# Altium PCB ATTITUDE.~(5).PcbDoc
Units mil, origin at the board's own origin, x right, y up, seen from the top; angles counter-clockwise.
Board outline 6000 x 4000 mil, 2 copper layers (Top Layer, Bottom Layer); 6 components, 40 nets, 83 pads, 0 vias.
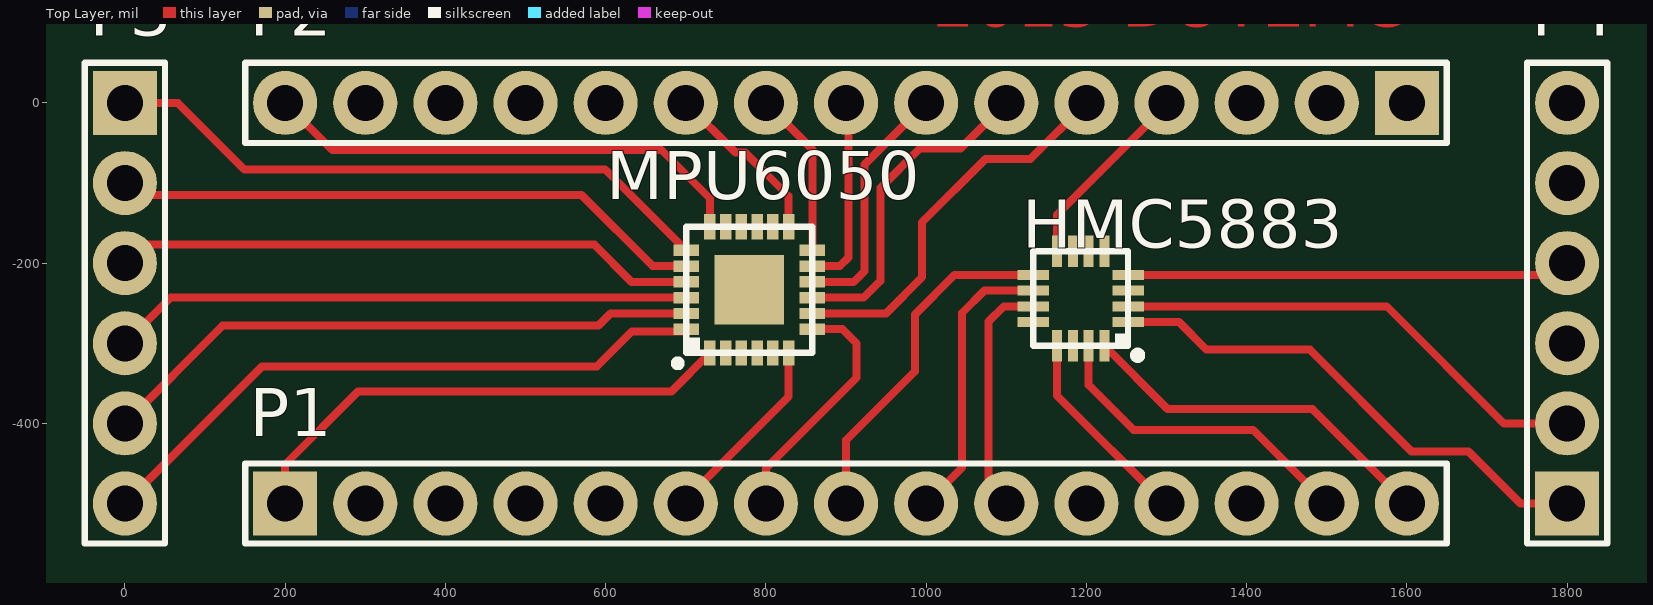
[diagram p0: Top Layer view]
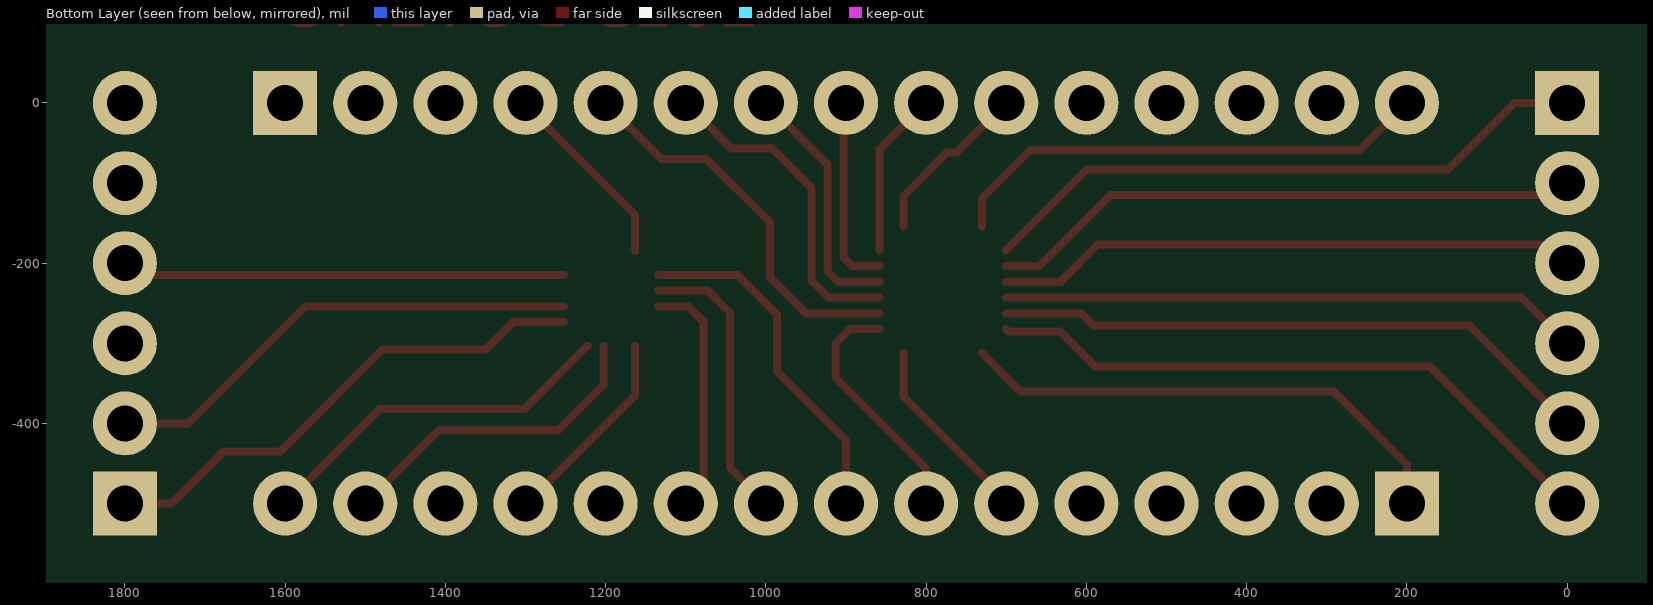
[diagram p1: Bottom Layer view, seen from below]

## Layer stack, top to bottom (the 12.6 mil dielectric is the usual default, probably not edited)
Top Solder: solder mask 0.4, Solder Resist, Dk 3.5
Top Layer: signal copper 1.4
Dielectric 1: dielectric 12.6, FR-4, Dk 4.8
Bottom Layer: signal copper 1.4
Bottom Solder: solder mask 0.4, Solder Resist, Dk 3.5

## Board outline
-436,-2862 5564,-2862 5564,1138 -436,1138

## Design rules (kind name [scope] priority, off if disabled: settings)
Clearance [All] p1: gap=10
PolygonConnect [All] p1: connectstyle=Relief reliefconductorwidth=10 reliefentries=4 polygonreliefangle="90 Angle" airgapwidth=10
RoutingVias [All] p1: holewidth=28 width=50 viastyle="Through Hole" minholewidth=28 minwidth=50 maxholewidth=28 maxwidth=50
SolderMaskExpansion [All] p1: expansion=4
Width [All] p1: maxlimit=10 minlimit=10 preferedwidth=10
29 further rules are at their usual default settings.

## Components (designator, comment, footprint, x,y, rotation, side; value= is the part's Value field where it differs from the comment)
HMC5883 "HMC5883" HMC5883 1252,-185 r180 top
MPU6050 "MPU6050" MPU6050 858,-312 r90 top
P1 "Header 15" HDR1X15 200,-500 r0 top
P2 "Header 15" HDR1X15 1600,0 r180 top
P3 "Header 6" HDR1X6 0,0 r270 top
P4 "Header 6" HDR1X6 1800,-500 r90 top

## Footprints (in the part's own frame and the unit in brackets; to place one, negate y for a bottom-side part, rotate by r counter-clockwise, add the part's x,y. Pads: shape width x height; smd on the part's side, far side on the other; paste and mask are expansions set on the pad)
HDR1X6 [mil] "Connector; Header; 6 Position"
  rect 80x80 hole 45: 1(0,0)
  round 80 hole 45: 2(100,0) 3(200,0) 4(300,0) 5(400,0) 6(500,0)
  silkscreen extent -50,-50 550,50
HDR1X15 [mil] "Connector; Header; 15 Position"
  rect 80x80 hole 45: 1(0,0)
  round 80 hole 45: 2(100,0) 3(200,0) 4(300,0) 5(400,0) 6(500,0) 7(600,0) 8(700,0) 9(800,0) 10(900,0) 11(1000,0) 12(1100,0) 13(1200,0) 14(1300,0) 15(1400,0)
  silkscreen extent -50,-50 1450,50
HMC5883 [mm]
  rect 1x0.32 smd: 1(0,2.25) 2(0,1.75) 3(0,1.25) 4(0,0.75) 9(3,0.75) 10(3,1.25) 11(3,1.75) 12(3,2.25)
  rect 0.32x1 smd: 5(0.75,0) 6(1.25,0) 7(1.75,0) 8(2.25,0) 13(2.25,3) 14(1.75,3) 15(1.25,3) 16(0.75,3)
  silkscreen extent -0.42,0 3,3.42
MPU6050 [mm]
  rect 0.8x0.36 smd: 1(0,3.25) 2(0,2.75) 3(0,2.25) 4(0,1.75) 5(0,1.25) 6(0,0.75) 13(4,0.75) 14(4,1.25) 15(4,1.75) 16(4,2.25) 17(4,2.75) 18(4,3.25)
  rect 0.36x0.8 smd: 7(0.75,0) 8(1.25,0) 9(1.75,0) 10(2.25,0) 11(2.75,0) 12(3.25,0) 19(3.25,4) 20(2.75,4) 21(2.25,4) 22(1.75,4) 23(1.25,4) 24(0.75,4)
  rect 2.2x2.2 smd: 25(2,2)
  silkscreen extent -0.42,0 4,4.36

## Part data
HMC5883 MPU6050: library part Component_1
P1 P2: "Header, 15-Pin"
P3 P4: "Header, 6-Pin"

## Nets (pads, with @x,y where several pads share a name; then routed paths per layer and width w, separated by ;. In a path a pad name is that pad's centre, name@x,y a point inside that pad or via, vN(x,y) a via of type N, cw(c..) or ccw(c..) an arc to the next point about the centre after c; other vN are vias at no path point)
HMC_1: HMC5883.1 P4.1 | length 641.8
  Top Layer w10: HMC5883.1 1315.58,-273.58 1350,-308 1479,-308 1606,-435 1677,-435 1742,-500 P4.1
HMC_2: HMC5883.2 P4.2 | length 608.5
  Top Layer w10: HMC5883.2 1574.9,-253.9 1721,-400 P4.2
HMC_3: P4.3
HMC_4: HMC5883.4 P4.4 | length 554
  Top Layer w10: HMC5883.4 1785.47,-214.53 P4.4
HMC_5: P2.1
HMC_6: P2.2
HMC_7: P2.3
HMC_8: HMC5883.8 P2.4 | length 241.6
  Top Layer w10: HMC5883.8 1163.42,-139.58 1300,-3 P2.4
HMC_9: HMC5883.9 P1.8 | length 440
  Top Layer w10: P1.8 900,-421 986,-335 986,-264 1035.47,-214.53 HMC5883.9
HMC_10: HMC5883.10 P1.9 | length 357
  Top Layer w10: P1.9 1045,-455 1045,-262 1072.79,-234.21 HMC5883.10
HMC_11: HMC5883.11 P1.10 | length 299.9
  Top Layer w10: P1.10 1078,-478 1078,-273 1097.1,-253.9 HMC5883.11
HMC_12: P1.11
HMC_13: HMC5883.13 P1.12 | length 254.6
  Top Layer w10: HMC5883.13 1163.42,-365.42 1298,-500 P1.12
HMC_14: P1.13
HMC_15: HMC5883.15 P1.14 | length 407.3
  Top Layer w10: HMC5883.15 1202.79,-351.79 1259,-408 1408,-408 P1.14
HMC_16: HMC5883.16 P1.15 | length 459.1
  Top Layer w10: HMC5883.16 1301.36,-382 1482,-382 P1.15
MPU_1: MPU6050.1 P1.1 | length 636.6
  Top Layer w10: P1.1 200,-451 291,-360 682.05,-360 MPU6050.1
MPU_2: P1.2
MPU_3: P1.3
MPU_4: P1.4
MPU_5: P1.5
MPU_6: MPU6050.6 P1.6 | length 241.2
  Top Layer w10: P1.6 700,-495 828.47,-366.53 MPU6050.6
MPU_7: MPU6050.7 P1.7 | length 309.1
  Top Layer w10: P1.7 800,-456 913,-343 913,-300 895.47,-282.47 MPU6050.7
MPU_8: MPU6050.8 P2.5 | length 491
  Top Layer w10: MPU6050.8 949.79,-262.79 995,-217.57 995,-149 1074,-70 1130,-70 P2.5
MPU_9: MPU6050.9 P2.6 | length 410.6
  Top Layer w10: MPU6050.9 921.9,-243.1 943,-222 943,-106 992,-57 1043,-57 P2.6
MPU_10: MPU6050.10 P2.7 | length 312.5
  Top Layer w10: MPU6050.10 909.58,-223.42 923,-210 923,-77 P2.7
MPU_11: MPU6050.11 P2.8 | length 243.7
  Top Layer w10: MPU6050.11 892.27,-203.73 903,-193 903,-3 P2.8
MPU_12: MPU6050.12 P2.9 | length 208.1
  Top Layer w10: P2.9 858,-58 MPU6050.12
MPU_13: MPU6050.13 P2.10 | length 214.8
  Top Layer w10: P2.10 762,-62 774,-62 828.47,-116.47 MPU6050.13
MPU_14: P2.11
MPU_15: P2.12
MPU_16: P2.13
MPU_17: P2.14
MPU_18: MPU6050.18 P2.15 | length 614.8
  Top Layer w10: P2.15 259,-59 670,-59 730.05,-119.05 MPU6050.18
MPU_19: MPU6050.19 P3.1 | length 776.8
  Top Layer w10: P3.1 66,0 149,-83 599.47,-83 MPU6050.19
MPU_20: MPU6050.20 P3.2 | length 743.5
  Top Layer w10: P3.2 15,-115 570,-115 658.73,-203.73 MPU6050.20
MPU_21: MPU6050.21 P3.3 | length 729.3
  Top Layer w10: P3.3 23,-177 586,-177 632.42,-223.42 MPU6050.21
MPU_22: MPU6050.22 P3.4 | length 724.1
  Top Layer w10: P3.4 56.9,-243.1 MPU6050.22
MPU_23: MPU6050.23 P3.5 | length 757.4
  Top Layer w10: P3.5 122,-278 591,-278 606.21,-262.79 MPU6050.23
MPU_24: MPU6050.24 P3.6 | length 790.6
  Top Layer w10: P3.6 171,-329 589,-329 633,-285 697.99,-285 MPU6050.24
pads on no net: HMC5883.3 HMC5883.5 HMC5883.6 HMC5883.7 HMC5883.12 HMC5883.14 MPU6050.2 MPU6050.3 MPU6050.4 MPU6050.5 MPU6050.14 MPU6050.15 MPU6050.16 MPU6050.17 MPU6050.25 P4.5 P4.6

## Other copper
Top Layer:
  text "2015 DUTEMC" at 1008,95 h60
